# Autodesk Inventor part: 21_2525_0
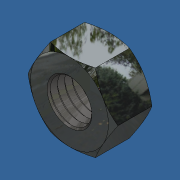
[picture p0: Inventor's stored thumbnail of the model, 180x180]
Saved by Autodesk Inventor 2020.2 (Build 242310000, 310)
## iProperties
Part Number: 21_2525_0
Material: Steel
Document SubType Name: Modeling
Designer: amoles
Appearance: Plate
Mass: 16.9019 g
Surface Area: 15.5817 cm^2
Volume: 2.15311 cm^3
Density: 7.85 g/cm^3
Author: amoles
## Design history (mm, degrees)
feature "Base1"
body "Solid1"
